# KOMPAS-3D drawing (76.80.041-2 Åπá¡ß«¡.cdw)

Referenced files in C:\Users\ptitsin\Desktop\Блок ПД 476 (160т)\: 76.80.041-2 Пуансон.cdw
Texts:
  Цементировать h 1...1.5 мм.; 54...58 HRCэ
  Полировать, х10, полировать
  Острые кромки притупить  1 мм.
  GOST2.303 6_RGB_0_0_0_SC_1_THICK_0.18
  невидимая2_RGB_0_0_0_SC_1_THICK_0.6
  невидимая2_RGB_255_0_0_SC_1_THICK_0.25
  GOST2.303 6_RGB_255_0_0_SC_1_THICK_0.25
  GOST2.303 5_RGB_255_0_0_SC_1_THICK_0.25
  Пуансон
  Сталь 12ХН3А ГОСТ 4543-71
  ООО "ЗАВОД МАРКОН"
Dimensions and other numbers on the sheet: 20; 10; 25; 45; 190; 150; 160; 230; 5; 140; 4 отв.; 0,03; 75; 35; 100; 40; 15; 1; 3 отв.; 16 отв.; 0.1; 8; 4; 1:1; 76.80.041-2; 76.80.041-2-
